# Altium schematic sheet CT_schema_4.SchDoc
size 406 x 311 mm
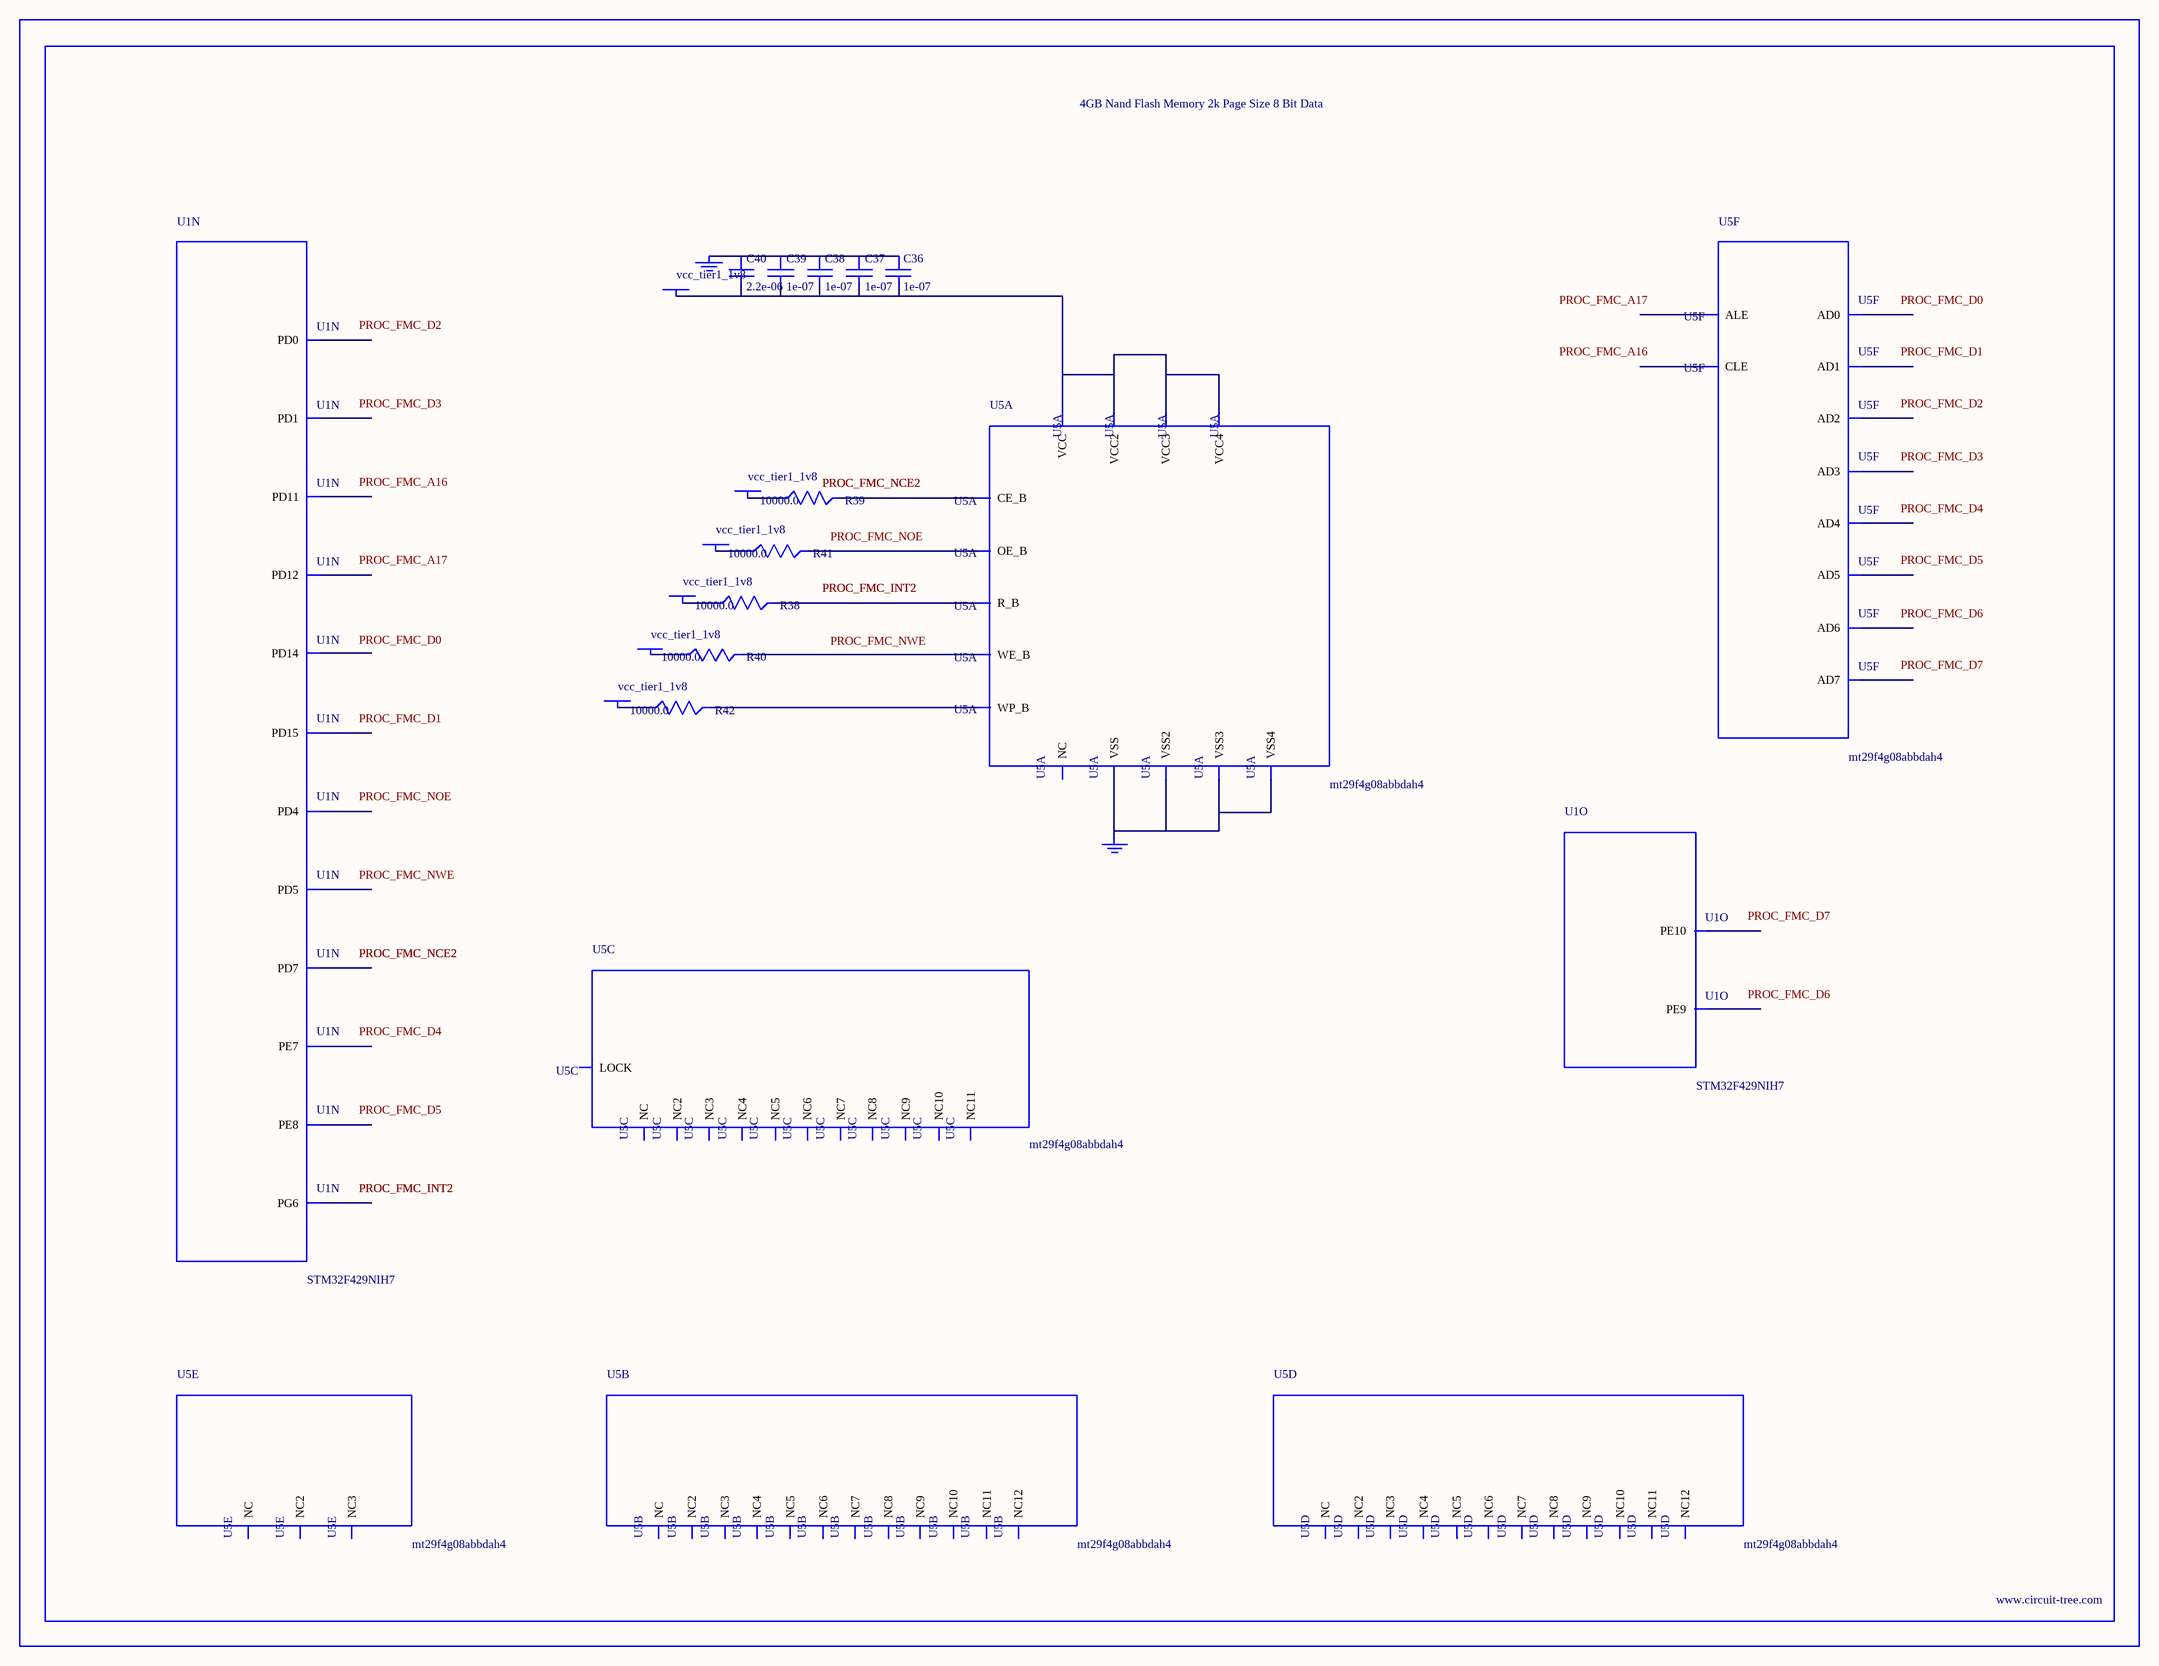
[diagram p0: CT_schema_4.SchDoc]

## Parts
BORDER3  (no value)
C36  1e-07  [C0402]
C37  1e-07  [C0402]
C38  1e-07  [C0402]
C39  1e-07  [C0402]
C40  2.2e-06  [C0603]
GND_INSTANCE_3_0  (no value)
GND_INSTANCE_3_1  (no value)
POWER_INSTANCE_3_0  vcc_tier1_1v8
POWER_INSTANCE_3_1  vcc_tier1_1v8
POWER_INSTANCE_3_2  vcc_tier1_1v8
POWER_INSTANCE_3_3  vcc_tier1_1v8
POWER_INSTANCE_3_4  vcc_tier1_1v8
POWER_INSTANCE_3_5  vcc_tier1_1v8
R38  10000.0  [R0603]
R39  10000.0  [R0603]
R40  10000.0  [R0603]
R41  10000.0  [R0603]
R42  10000.0  [R0603]
U1  STM32F429NIH7  [TFBGA216]  (parts N,O of 16)
U5  mt29f4g08abbdah4  [VFBGA-63]  (parts A,B,C,D,E,F of 6)

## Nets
NetC36_1: C36.1 C37.1 C38.1 C39.1 C40.1 GND_INSTANCE_3_0.0(GND)
NetC36_2: C36.2 C37.2 C38.2 C39.2 C40.2 POWER_INSTANCE_3_0.0(PWR) U5.D3(VCC) U5.G4(VCC2) U5.H8(VCC3) U5.J6(VCC4)
NetGND_INSTANCE_3_1_0: GND_INSTANCE_3_1.0(GND) U5.C5(VSS) U5.F7(VSS2) U5.K3(VSS3) U5.K8(VSS4)
NetPOWER_INSTANCE_3_1_0: POWER_INSTANCE_3_1.0(PWR) R38.1
NetPOWER_INSTANCE_3_2_0: POWER_INSTANCE_3_2.0(PWR) R39.1
NetPOWER_INSTANCE_3_3_0: POWER_INSTANCE_3_3.0(PWR) R40.1
NetPOWER_INSTANCE_3_4_0: POWER_INSTANCE_3_4.0(PWR) R41.1
NetPOWER_INSTANCE_3_5_0: POWER_INSTANCE_3_5.0(PWR) R42.1
NetR38_2: R38.2 U5.C8(R_B)
NetR39_2: R39.2 U5.C6(CE_B)
NetR40_2: R40.2 U5.C7(WE_B)
NetR41_2: R41.2 U5.D4(OE_B)
NetR42_2: R42.2 U5.C3(WP_B)

Not connected (* = marked no-connect by the designer): U1 A11(PD7) B12(PD0) C10(PD5) C12(PD1) D11(PD4) J15(PG6) K13(PD15) L12(PD14) M10(PD12) N9(PE8) N10(PD11) P9(PE9) R8(PE7) R9(PE10); U5 A1(NC) A2(NC3) A9(NC4) A10(NC2) B1(NC5) B9(NC7) B10(NC6) C4(ALE) D5(CLE) D6(NC8) D7(NC9) D8(NC10) E3(NC11) E4(NC12) E5(NC) E6(NC2) E7(NC3) E8(NC4) F3(NC5) F4(NC6) F5(NC7) F6(NC8) F8(NC9) G3(NC) G5(LOCK) G6(NC10) G7(NC11) G8(NC) H3(NC2) H4(AD0) H5(NC3) H6(NC4) H7(NC5) J3(NC6) J4(AD1) J5(NC7) J7(AD5) J8(AD7) K4(AD2) K5(AD3) K6(AD4) K7(AD6) L1(NC8) L2(NC10) L9(NC11) L10(NC9) M1(NC12) M2(NC2) M9(NC3) M10(NC)

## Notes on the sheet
- Labels drawn without touching a wire or pin: PROC_FMC_A16, PROC_FMC_A17, PROC_FMC_D0, PROC_FMC_D1, PROC_FMC_D2, PROC_FMC_D3, PROC_FMC_D4, PROC_FMC_D5, PROC_FMC_D6, PROC_FMC_D7, PROC_FMC_NOE, PROC_FMC_NWE

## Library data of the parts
BORDER3 = BORDER_PAGE3
C36-C39 = C0402C104K3RACTU
C40 = C0603C225K8RACTU
GND_INSTANCE_3_0 GND_INSTANCE_3_1 = GND
POWER_INSTANCE_3_0-POWER_INSTANCE_3_5 = PWR
R38-R42 = RC0603JR-0710KL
